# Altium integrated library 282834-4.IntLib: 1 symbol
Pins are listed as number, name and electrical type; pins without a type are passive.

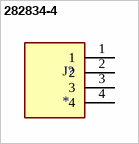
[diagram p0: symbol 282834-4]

## 282834-4
designator J?
4 Position Wire to Board Terminal Block Horizontal with Board 0.100 (2.54mm) Through Hole; MP: 282834-4; MF: TE Connectivity
footprint TE_282834-4
pins: 1, 2, 3, 4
